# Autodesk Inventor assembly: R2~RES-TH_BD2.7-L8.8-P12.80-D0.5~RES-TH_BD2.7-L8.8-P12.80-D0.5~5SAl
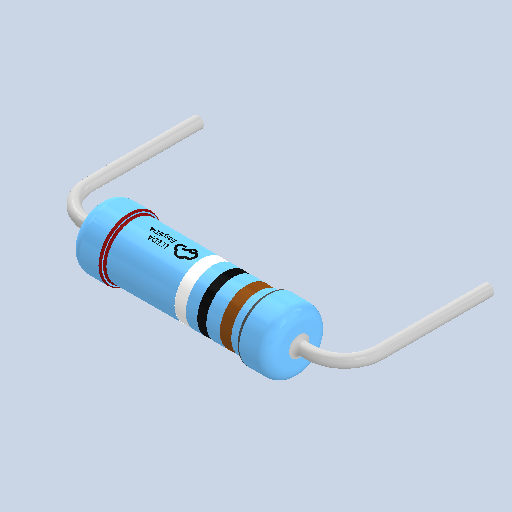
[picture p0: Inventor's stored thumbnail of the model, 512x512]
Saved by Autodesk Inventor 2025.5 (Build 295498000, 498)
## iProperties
Created: 2026-10
Part Number: R2~RES-TH_BD2.7-L8.8-P12.80-D0.5~RES-TH_BD2.7-L8.8-P12.80-D0.5~5SAl
Document SubType Name: Assembly
Designer: Luis M
Author: Luis M
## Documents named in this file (2)
- C:\Users\Luis M\Downloads\3D_PCB1_2026-10-28\R2~RES-TH_BD2.7-L8.8-P12.80-D0.5~RES-TH_BD2.7-L8.8-P12.80-D0.5~5SAl.iam
- C:\Users\Luis M\Downloads\3D_PCB1_2026-10-28\RES-TH_BD2.7-L8.8-P12.80-D0.5~RES-TH_BD2.7-L8.8-P12.80-D0.5~UAzC.ipt
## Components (1 placed, 1 different names)
1. R2->0
